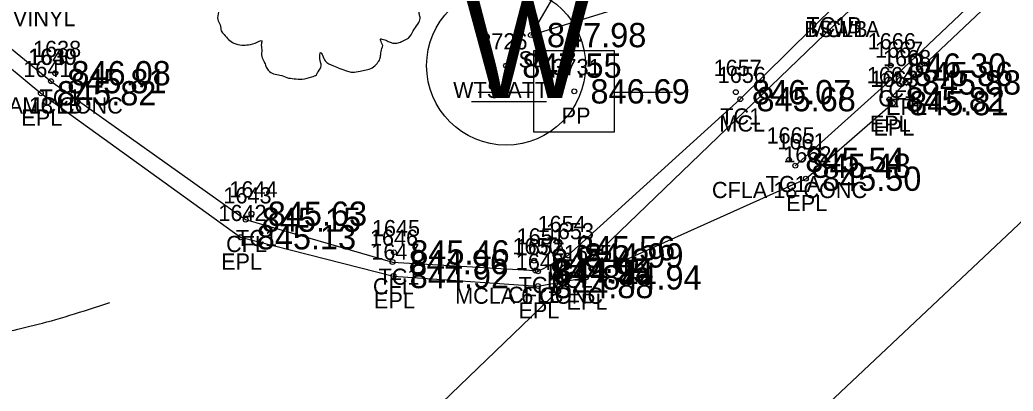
# Model space of a CAD drawing. Extents: x 1622501 to 1626664, y 1117816 to 1121579.
# Drawn here: x 1624849.5 to 1624910.8, y 1120113.7 to 1120136.6 of the extents above; entities that cross this region are included whole.
import ezdxf

# ---------------------------------------------------------------- set-up
doc = ezdxf.new("R2010")
doc.units = 0
for name, color, linetype in [('RD_EX_Conc', 7, 'Continuous'), ('RD_EX_Conc_txCode', 7, 'Continuous'), ('RD_EX_DR_Pipe', 7, 'Continuous'), ('RD_EX_Fence_Other_txCode', 7, 'Continuous'), ('RD_EX_Road', 7, 'Continuous'), ('RD_EX_Road_txCode', 7, 'Continuous'), ('RD_EX_SU_Telecom', 7, 'Continuous'), ('RD_EX_TX_Conc_ELEV', 7, 'Continuous'), ('RD_EX_TX_Road_ELEV', 7, 'Continuous'), ('RD_EX_TX_UT_ELEV', 7, 'Continuous'), ('RD_EX_TX_VEG_ELEV', 7, 'Continuous'), ('RD_EX_UT', 7, 'Continuous'), ('RD_EX_UT_txCode', 7, 'Continuous'), ('RD_EX_VEG', 7, 'Continuous'), ('RD_EX_VEG_txCode', 7, 'Continuous'), ('RD_HC_Cl', 7, 'Continuous'), ('RD_HC_Survey_ELEV', 7, 'Continuous'), ('RD_SMD_Locator', 7, 'Continuous')]:
    doc.layers.add(name, color=color, linetype=linetype)

msp = doc.modelspace()

# ---------------------------------------------------------------- linework, layer by layer
at = {"layer": 'RD_EX_Conc'}
for points in [[(1624897.378, 1120127.586), (1624903.697, 1120133.247), (1624939.766, 1120167.411), (1624977.137, 1120202.764), (1625013.589, 1120237.139), (1625049.488, 1120270.838), (1625084.275, 1120303.479), (1625121.787, 1120338.741), (1625157.607, 1120372.541), (1625193.027, 1120405.896), (1625230.27, 1120441.109), (1625263.987, 1120473.049), (1625301.798, 1120509.249), (1625336.15, 1120542.221), (1625372.25, 1120576.993), (1625405.365, 1120609.311), (1625409.32, 1120614.519), (1625412.456, 1120620.32), (1625414.419, 1120627.016), (1625414.966, 1120636.138), (1625412.914, 1120644.37), (1625411.037, 1120648.086), (1625399.274, 1120667.189)], [(1624782.174, 1120199.047), (1624784.892, 1120189.449), (1624788.803, 1120184.422), (1624820.359, 1120158.326), (1624851.407, 1120132.805)], [(1624881.483, 1120121.063), (1624883.336, 1120122.047), (1624893.977, 1120131.693), (1624899.89, 1120137.526)], [(1624851.407, 1120132.805), (1624863.428, 1120124.255), (1624872.499, 1120121.64), (1624881.319, 1120121.117)]]:
    msp.add_lwpolyline(points, dxfattribs=at)
at = {"layer": 'RD_EX_DR_Pipe'}
msp.add_lwpolyline([(1625495.159, 1120700.169), (1625478.481, 1120693.944), (1625478.481, 1120693.944), (1625401.274, 1120618.609), (1625386.855, 1120595.889), (1625386.855, 1120595.889), (1625239.336, 1120454.576), (1625067.489, 1120292.506), (1624913.323, 1120147.082), (1624906.318, 1120142.577), (1624803.571, 1120043.734), (1624612.212, 1119870.34), (1624528.295, 1119793.118)], dxfattribs=at)
at = {"layer": 'RD_EX_Road'}
msp.add_lwpolyline([(1624781.367, 1120199.017), (1624784.165, 1120188.994), (1624788.317, 1120183.838), (1624819.769, 1120157.812), (1624850.784, 1120132.057), (1624863.119, 1120123.17), (1624872.562, 1120120.776), (1624881.482, 1120120.158), (1624884.455, 1120120.692), (1624898.026, 1120126.784), (1624903.404, 1120131.449), (1624903.183, 1120131.678), (1624904.185, 1120132.725), (1624940.396, 1120166.874), (1624977.651, 1120202.124), (1625014.07, 1120236.514), (1625050.075, 1120270.322), (1625084.777, 1120302.734), (1625122.295, 1120338.035), (1625158.189, 1120371.975), (1625193.609, 1120405.268), (1625230.886, 1120440.454)], dxfattribs=at)
at = {"layer": 'RD_EX_SU_Telecom'}
msp.add_open_spline([(1624838.999, 1120117.818), (1624841.003, 1120118.917), (1624845.685, 1120115.968), (1624855.05, 1120119.148)], degree=2, dxfattribs=at)
at = {"layer": 'RD_EX_UT'}
for p, q in [((1624886.215, 1120134.683), (1624881.215, 1120134.683)), ((1624881.215, 1120134.683), (1624881.215, 1120129.683)), ((1624886.215, 1120129.683), (1624886.215, 1120134.683)), ((1624877.784, 1120132.121), (1624881.254, 1120132.121)), ((1624886.144, 1120132.121), (1624889.784, 1120132.121)), ((1624877.386, 1120131.554), (1624882.015, 1120131.554)), ((1624881.215, 1120129.683), (1624886.215, 1120129.683))]:
    msp.add_line(p, q, dxfattribs=at)
msp.add_circle((1624879.514, 1120133.762), 4.908, dxfattribs=at)
at = {"layer": 'RD_EX_VEG'}
msp.add_lwpolyline([(1624889.699, 1120150.412), (1624881.041, 1120135.648), (1624900.095, 1120141.509), (1624901.078, 1120146.7)], dxfattribs=at)
for points in [[(1624867.677, 1120147.496), (1624867.377, 1120147.521), (1624867.052, 1120147.421), (1624866.802, 1120147.321), (1624866.577, 1120147.246), (1624866.352, 1120147.146), (1624866.052, 1120146.971), (1624865.827, 1120146.771), (1624865.702, 1120146.522), (1624865.652, 1120146.297), (1624865.602, 1120146.022), (1624865.602, 1120145.847), (1624865.478, 1120145.822), (1624865.328, 1120145.847), (1624865.078, 1120145.922), (1624864.828, 1120145.922), (1624864.578, 1120145.922), (1624864.228, 1120145.897), (1624863.878, 1120145.897), (1624863.603, 1120145.847), (1624863.278, 1120145.797), (1624862.904, 1120145.672), (1624862.554, 1120145.547), (1624862.254, 1120145.297), (1624862.004, 1120144.822), (1624861.879, 1120144.472), (1624861.729, 1120144.223), (1624861.879, 1120143.773), (1624862.054, 1120143.423), (1624862.079, 1120143.223), (1624862.154, 1120142.798), (1624862.254, 1120142.573), (1624862.379, 1120142.373), (1624862.304, 1120142.348), (1624861.929, 1120142.298), (1624861.629, 1120142.198), (1624861.204, 1120141.974), (1624860.979, 1120141.749), (1624860.879, 1120141.424), (1624860.855, 1120141.074), (1624860.755, 1120140.874), (1624860.68, 1120140.599), (1624860.655, 1120140.524), (1624860.605, 1120140.199), (1624860.705, 1120139.749), (1624860.73, 1120139.4), (1624860.855, 1120139.175), (1624861.004, 1120139), (1624861.179, 1120138.75), (1624861.579, 1120138.525), (1624861.904, 1120138.425), (1624862.104, 1120138.4), (1624861.929, 1120137.9), (1624861.879, 1120137.55), (1624861.754, 1120137.151), (1624861.754, 1120137.076), (1624861.704, 1120136.601), (1624861.854, 1120136.276), (1624861.929, 1120135.901), (1624862.104, 1120135.676), (1624862.379, 1120135.376), (1624862.704, 1120135.152), (1624863.204, 1120135.027), (1624863.603, 1120135.052), (1624864.178, 1120135.226), (1624864.428, 1120135.301), (1624864.403, 1120135.127), (1624864.428, 1120134.752), (1624864.428, 1120134.327), (1624864.578, 1120134.002), (1624864.678, 1120133.727), (1624864.828, 1120133.477), (1624865.153, 1120133.252), (1624865.552, 1120133.177), (1624865.977, 1120133.027), (1624866.427, 1120132.952), (1624866.927, 1120132.927), (1624867.527, 1120133.077), (1624867.801, 1120133.202), (1624867.901, 1120133.377), (1624868.101, 1120133.752), (1624868.051, 1120133.977), (1624868.076, 1120134.577), (1624868.176, 1120134.402), (1624868.351, 1120134.052), (1624868.851, 1120133.752), (1624869.251, 1120133.577), (1624869.726, 1120133.427), (1624870.026, 1120133.352), (1624870.5, 1120133.427), (1624870.875, 1120133.502), (1624871.25, 1120133.627), (1624871.55, 1120133.902), (1624871.725, 1120134.177), (1624871.775, 1120134.452), (1624871.85, 1120134.827), (1624871.9, 1120135.002)], [(1624871.9, 1120135.002), (1624871.825, 1120135.177), (1624871.775, 1120135.426), (1624871.85, 1120135.401), (1624872.025, 1120135.351), (1624872.3, 1120135.226), (1624872.524, 1120135.152), (1624872.849, 1120135.177), (1624873.124, 1120135.276), (1624873.574, 1120135.551), (1624873.849, 1120136.026), (1624874.124, 1120136.426), (1624874.199, 1120136.751), (1624874.149, 1120136.976), (1624874.124, 1120137.475), (1624873.924, 1120137.725), (1624873.874, 1120137.85), (1624873.774, 1120138.25), (1624873.849, 1120138.3), (1624874.124, 1120138.35), (1624874.499, 1120138.475), (1624874.773, 1120138.6), (1624874.998, 1120138.775), (1624875.073, 1120139), (1624875.048, 1120139.4), (1624875.098, 1120139.799), (1624875.023, 1120139.949), (1624874.923, 1120140.099), (1624874.848, 1120140.299), (1624874.698, 1120140.449), (1624874.599, 1120140.599), (1624874.499, 1120140.699), (1624874.374, 1120140.849), (1624874.199, 1120140.974), (1624874.049, 1120141.024), (1624873.999, 1120141.174), (1624874.149, 1120141.374), (1624874.199, 1120141.474), (1624874.224, 1120141.699), (1624874.449, 1120142.048), (1624874.499, 1120142.448), (1624874.449, 1120142.873), (1624874.399, 1120143.148), (1624874.249, 1120143.423), (1624874.049, 1120143.673), (1624873.924, 1120143.848), (1624873.749, 1120143.973), (1624873.424, 1120144.098), (1624873.174, 1120144.148), (1624872.824, 1120144.148), (1624872.624, 1120144.198), (1624872.649, 1120144.248), (1624872.649, 1120144.397), (1624872.649, 1120144.672), (1624872.574, 1120145.122), (1624872.424, 1120145.622), (1624872.424, 1120145.647), (1624872.324, 1120145.897), (1624872.1, 1120146.097), (1624871.925, 1120146.197), (1624871.725, 1120146.322), (1624871.475, 1120146.347), (1624871.175, 1120146.347), (1624870.9, 1120146.297), (1624870.7, 1120146.197), (1624870.525, 1120146.072), (1624870.45, 1120146.222), (1624870.35, 1120146.522), (1624870.3, 1120146.671), (1624870.15, 1120146.846), (1624869.926, 1120147.046), (1624869.476, 1120147.171), (1624868.851, 1120147.096), (1624868.551, 1120146.896), (1624868.401, 1120146.721), (1624868.351, 1120146.846), (1624868.151, 1120147.046), (1624868.051, 1120147.221), (1624867.876, 1120147.346), (1624867.727, 1120147.446), (1624867.627, 1120147.496)]]:
    msp.add_spline(points, degree=3, dxfattribs=at)
at = {"layer": 'RD_HC_Cl'}
msp.add_line((1624870.491, 1120085.684), (1625124.669, 1120324.937), dxfattribs=at)
at = {"layer": 'RD_SMD_Locator'}
for centre in [(1624881.041, 1120135.648), (1624879.515, 1120133.762), (1624903.266, 1120133.768), (1624851.668, 1120133.295), (1624903.697, 1120133.247), (1624851.407, 1120132.805), (1624851.407, 1120132.805), (1624904.185, 1120132.725), (1624850.784, 1120132.057), (1624883.725, 1120132.174), (1624893.7, 1120132.125), (1624893.977, 1120131.693), (1624903.183, 1120131.678), (1624903.404, 1120131.449), (1624896.992, 1120127.955), (1624897.378, 1120127.586), (1624898.026, 1120126.784), (1624863.796, 1120124.624), (1624863.428, 1120124.255), (1624863.119, 1120123.17), (1624882.828, 1120122.491), (1624872.598, 1120122.234), (1624883.336, 1120122.047), (1624872.499, 1120121.64), (1624881.252, 1120121.722), (1624872.562, 1120120.776), (1624881.319, 1120121.117), (1624881.483, 1120121.063), (1624884.455, 1120120.692), (1624881.482, 1120120.158)]:
    msp.add_circle(centre, 0.15, dxfattribs=at)

# ---------------------------------------------------------------- texts
at = {"layer": 'RD_EX_Conc_txCode'}
for s, p in [('TC1B', (1624898.059, 1120135.758)), ('BSW1A', (1624897.921, 1120135.526)), ('MCLB', (1624898.126, 1120135.526)), ('1666', (1624901.848, 1120134.768)), ('1638', (1624850.298, 1120134.295)), ('1667', (1624902.303, 1120134.247)), ('1640', (1624849.997, 1120133.805)), ('1639', (1624850.036, 1120133.805)), ('1657', (1624892.33, 1120133.125)), ('1656', (1624892.583, 1120132.693)), ('TC1', (1624902.305, 1120131.768)), ('TC1', (1624850.708, 1120131.295)), ('CFL', (1624902.492, 1120131.247)), ('CFLA 18 CONC', (1624846.257, 1120130.805)), ('MCLB', (1624849.643, 1120130.805)), ('TC1', (1624892.74, 1120130.125)), ('MCL', (1624892.685, 1120129.693)), ('1665', (1624895.599, 1120128.955)), ('1661', (1624896.268, 1120128.586)), ('TC1A', (1624895.544, 1120125.955)), ('1644', (1624862.425, 1120125.624)), ('CFLA 18 CONC', (1624892.228, 1120125.586)), ('1643', (1624862.058, 1120125.255)), ('1654', (1624881.457, 1120123.491)), ('1645', (1624871.228, 1120123.234)), ('1653', (1624881.965, 1120123.047)), ('CFL', (1624862.223, 1120122.255)), ('TC1', (1624862.835, 1120122.624)), ('1646', (1624871.105, 1120122.64)), ('1651', (1624880.165, 1120122.722)), ('1650', (1624879.91, 1120122.117)), ('1652', (1624880.113, 1120122.063)), ('TC1', (1624881.867, 1120120.491)), ('TC1', (1624871.637, 1120120.234)), ('MCL', (1624882.044, 1120120.047)), ('CFL', (1624871.294, 1120119.64)), ('TC1', (1624880.291, 1120119.722)), ('MCLA 6 CONC', (1624876.364, 1120119.063)), ('CFLB', (1624879.642, 1120119.117))]:
    msp.add_text(s, height=1, dxfattribs=at).set_placement(p)
at = {"layer": 'RD_EX_Fence_Other_txCode'}
msp.add_text('FL1A 48 VINYL', height=1, dxfattribs=at).set_placement((1624843.63, 1120136.192))
at = {"layer": 'RD_EX_Road_txCode'}
for s, p in [('1668', (1624902.791, 1120133.725)), ('1641', (1624849.697, 1120133.057)), ('1664', (1624901.789, 1120132.678)), ('1663', (1624902.01, 1120132.449)), ('EPL', (1624902.98, 1120130.725)), ('EPL', (1624849.579, 1120130.057)), ('EPL', (1624901.978, 1120129.678)), ('EPL', (1624902.199, 1120129.449)), ('1662', (1624896.632, 1120127.784)), ('EPL', (1624896.821, 1120124.784)), ('1642', (1624861.748, 1120124.17)), ('1647', (1624871.192, 1120121.776)), ('1655', (1624883.085, 1120121.692)), ('EPL', (1624861.914, 1120121.17)), ('1649', (1624880.112, 1120121.158)), ('EPL', (1624871.357, 1120118.776)), ('EPL', (1624883.25, 1120118.692)), ('EPL', (1624880.278, 1120118.158))]:
    msp.add_text(s, height=1, dxfattribs=at).set_placement(p)
at = {"layer": 'RD_EX_TX_Conc_ELEV'}
for s, p in [('846.30', (1624904.266, 1120133.018)), ('846.08', (1624852.668, 1120132.545)), ('845.86', (1624904.697, 1120132.497)), ('845.81', (1624852.407, 1120132.055)), ('845.81', (1624852.407, 1120132.055)), ('846.07', (1624894.7, 1120131.375)), ('845.68', (1624894.977, 1120130.943)), ('845.54', (1624897.992, 1120127.205)), ('845.48', (1624898.378, 1120126.836)), ('845.63', (1624864.796, 1120123.874)), ('845.15', (1624864.428, 1120123.505)), ('845.56', (1624883.828, 1120121.741)), ('845.46', (1624873.598, 1120121.484)), ('844.99', (1624884.336, 1120121.297)), ('844.96', (1624873.499, 1120120.89)), ('845.42', (1624882.252, 1120120.972)), ('844.95', (1624882.319, 1120120.367)), ('844.94', (1624882.483, 1120120.313))]:
    msp.add_text(s, height=1.5, dxfattribs=at).set_placement(p)
at = {"layer": 'RD_EX_TX_Road_ELEV'}
for s, p in [('845.88', (1624905.185, 1120131.975)), ('845.82', (1624851.784, 1120131.307)), ('845.82', (1624904.183, 1120130.928)), ('845.81', (1624904.404, 1120130.699)), ('845.50', (1624899.026, 1120126.034)), ('845.13', (1624864.119, 1120122.42)), ('844.92', (1624873.562, 1120120.026)), ('844.94', (1624885.455, 1120119.942)), ('844.88', (1624882.482, 1120119.408))]:
    msp.add_text(s, height=1.5, dxfattribs=at).set_placement(p)
at = {"layer": 'RD_EX_TX_UT_ELEV'}
msp.add_text('847.55', height=1.5, dxfattribs=at).set_placement((1624880.515, 1120133.012))
at = {"layer": 'RD_EX_TX_VEG_ELEV'}
msp.add_text('847.98', height=1.5, dxfattribs=at).set_placement((1624882.041, 1120134.898))
at = {"layer": 'RD_EX_UT'}
msp.add_text('W', height=6, dxfattribs=at).set_placement((1624877.05, 1120131.761))
at = {"layer": 'RD_EX_UT_txCode'}
for s, p in [('3726', (1624877.861, 1120134.762)), ('3731', (1624882.378, 1120133.174)), ('WTS ATT', (1624876.247, 1120131.762)), ('PP', (1624882.945, 1120130.174))]:
    msp.add_text(s, height=1, dxfattribs=at).set_placement(p)
at = {"layer": 'RD_EX_VEG_txCode'}
msp.add_text('SL', height=1, dxfattribs=at).set_placement((1624880.285, 1120133.648))
at = {"layer": 'RD_HC_Survey_ELEV'}
msp.add_text('846.69', height=1.5, dxfattribs=at).set_placement((1624884.725, 1120131.424))

doc.saveas('drawing.dxf')
